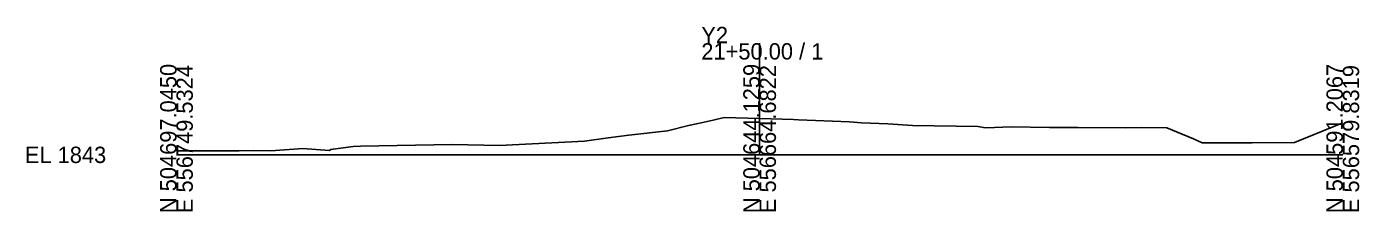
# Model space of a CAD drawing. Extents: x -26 to 203, y -10 to 3574.
# Drawn here: x -25.7 to 202.8, y 1490.3 to 1522 of the extents above; entities that cross this region are included whole.
import ezdxf

# ---------------------------------------------------------------- set-up
doc = ezdxf.new("R2010")
doc.units = 0
doc.layers.add('Exist Cross Section Cell', color=7, linetype='Continuous')
doc.layers.add('Exist XS Ground Line', color=7, linetype='Continuous')

msp = doc.modelspace()

# ---------------------------------------------------------------- linework, layer by layer
at = {"layer": 'Exist Cross Section Cell'}
for p, q in [((100, 1500), (100, 1519.15)), ((0, 1500), (100, 1500)), ((100, 1500), (200, 1500))]:
    msp.add_line(p, q, dxfattribs=at)
at = {"layer": 'Exist XS Ground Line'}
for p, q in [((92.03, 1505.97), (93.89, 1506.38)), ((93.89, 1506.38), (100, 1506.22)), ((100, 1506.22), (105.83, 1506.07)), ((105.83, 1506.07), (106.69, 1506.03)), ((77.57, 1503.37), (84.22, 1504.13)), ((84.22, 1504.13), (87.78, 1505.03)), ((87.78, 1505.03), (89.45, 1505.4)), ((89.45, 1505.4), (92.03, 1505.97)), ((106.69, 1506.03), (115.43, 1505.65)), ((115.43, 1505.65), (117.46, 1505.51)), ((117.46, 1505.51), (122.01, 1505.31)), ((122.01, 1505.31), (126.23, 1505.03)), ((126.23, 1505.03), (137.44, 1504.85)), ((137.44, 1504.85), (138.73, 1504.61)), ((138.73, 1504.61), (140.27, 1504.68)), ((140.27, 1504.68), (143.12, 1504.79)), ((143.12, 1504.79), (149.7, 1504.69)), ((149.7, 1504.69), (154.57, 1504.7)), ((154.57, 1504.7), (162.66, 1504.66)), ((162.66, 1504.66), (165.56, 1504.68)), ((165.56, 1504.68), (169.83, 1504.64)), ((169.83, 1504.64), (174.39, 1502.74)), ((191.72, 1502.1), (200, 1505.47)), ((30.28, 1501.45), (31.53, 1501.49)), ((31.53, 1501.49), (47.26, 1501.76)), ((47.26, 1501.76), (55.39, 1501.62)), ((55.39, 1501.62), (69.99, 1502.36)), ((69.99, 1502.36), (74.02, 1502.92)), ((74.02, 1502.92), (77.57, 1503.37)), ((174.39, 1502.74), (175.87, 1502.05)), ((175.87, 1502.05), (178.43, 1502.06)), ((178.43, 1502.06), (184.44, 1502.07)), ((184.44, 1502.07), (191.72, 1502.1)), ((0, 1500.69), (10.74, 1500.66)), ((10.74, 1500.66), (13.25, 1500.73)), ((13.25, 1500.73), (16.17, 1500.67)), ((16.17, 1500.67), (21.68, 1501.07)), ((21.68, 1501.07), (26.25, 1500.74)), ((26.25, 1500.74), (26.49, 1500.94)), ((26.49, 1500.94), (30.28, 1501.45))]:
    msp.add_line(p, q, dxfattribs=at)

# ---------------------------------------------------------------- texts
at = {"layer": 'Exist Cross Section Cell'}
for s, p in [('Y2', (90, 1519.15)), ('21+50.00 / 1', (90, 1516.35)), ('EL 1843', (-26, 1498.6))]:
    msp.add_text(s, height=2.8, dxfattribs=at).set_placement(p)
for s, p in [('N 504697.0450', (0, 1490)), ('E 556749.5324', (2.8, 1490)), ('N 504644.1259', (100, 1490)), ('E 556664.6822', (102.8, 1490)), ('N 504591.2067', (200, 1490)), ('E 556579.8319', (202.8, 1490))]:
    msp.add_text(s, height=2.8, rotation=90, dxfattribs=at).set_placement(p)

doc.saveas('drawing.dxf')
